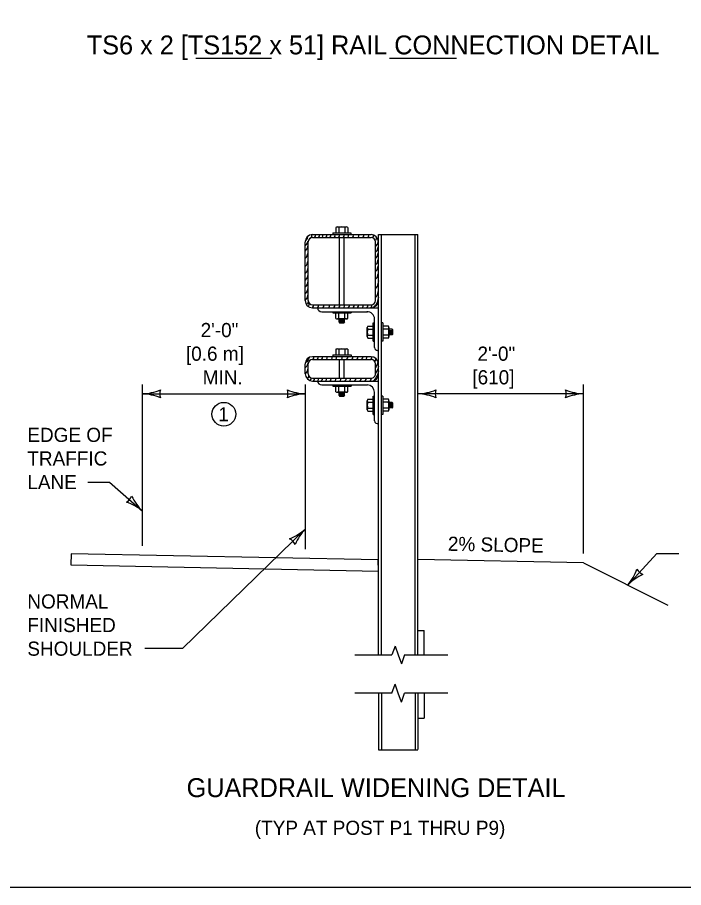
# Model space of a CAD drawing. Extents: x 49991.4 to 50021, y 49987.6 to 50011.4.
# Drawn here: x 50011.156 to 50013.977, y 49987.799 to 49991.484 of the extents above; entities that cross this region are included whole.
import ezdxf

# ---------------------------------------------------------------- set-up
doc = ezdxf.new("R2010")
doc.units = 0
for name, color, linetype in [('Level 1', 7, 'Continuous'), ('Level 2', 7, 'Continuous'), ('Level 3', 7, 'Continuous'), ('Level 6', 7, 'Continuous')]:
    doc.layers.add(name, color=color, linetype=linetype)

msp = doc.modelspace()

# ---------------------------------------------------------------- linework, layer by layer
at = {"layer": 'Level 1'}
for p, q in [((50012.4056, 49990.5649), (50012.6532, 49990.5649)), ((50012.4907, 49990.5713), (50012.5683, 49990.5713)), ((50012.4907, 49990.5713), (50012.4907, 49990.5649)), ((50012.5038, 49990.595), (50012.5038, 49990.5713)), ((50012.5038, 49990.5713), (50012.555, 49990.5713)), ((50012.5102, 49990.5966), (50012.5485, 49990.5966)), ((50012.5165, 49990.595), (50012.5165, 49990.5714)), ((50012.5423, 49990.595), (50012.5423, 49990.5714)), ((50012.555, 49990.595), (50012.555, 49990.5713)), ((50012.5683, 49990.5713), (50012.5683, 49990.5649)), ((50012.6848, 49990.5649), (50012.852, 49990.5649)), ((50012.6848, 49988.7839), (50012.6848, 49990.5649)), ((50012.6971, 49988.7839), (50012.6971, 49990.5649)), ((50012.8399, 49988.7839), (50012.8399, 49990.5649)), ((50012.852, 49988.7839), (50012.852, 49990.5649)), ((50012.3744, 49990.285), (50012.3744, 49990.5333)), ((50012.3865, 49990.285), (50012.3865, 49990.5333)), ((50012.4056, 49990.5523), (50012.6532, 49990.5523)), ((50012.5197, 49990.2665), (50012.5197, 49990.5523)), ((50012.5233, 49990.5523), (50012.5356, 49990.5523)), ((50012.5391, 49990.2665), (50012.5391, 49990.5523)), ((50012.6723, 49990.285), (50012.6723, 49990.5333)), ((50012.6848, 49990.285), (50012.6848, 49990.5333)), ((50012.4056, 49990.2665), (50012.6532, 49990.2665)), ((50012.4056, 49990.2543), (50012.6848, 49990.2543)), ((50012.4448, 49990.2379), (50012.6375, 49990.2379)), ((50012.491, 49990.2379), (50012.491, 49990.2323)), ((50012.491, 49990.2323), (50012.5686, 49990.2323)), ((50012.5553, 49990.2323), (50012.5041, 49990.2323)), ((50012.5041, 49990.2086), (50012.5041, 49990.2323)), ((50012.5168, 49990.2086), (50012.5168, 49990.2322)), ((50012.5426, 49990.2086), (50012.5426, 49990.2322)), ((50012.5553, 49990.2086), (50012.5553, 49990.2323)), ((50012.5686, 49990.2379), (50012.5686, 49990.2323)), ((50012.5489, 49990.207), (50012.5106, 49990.207)), ((50012.518, 49990.1931), (50012.518, 49990.207)), ((50012.5414, 49990.1931), (50012.518, 49990.1931)), ((50012.518, 49990.1931), (50012.5203, 49990.1908)), ((50012.5214, 49990.2037), (50012.5379, 49990.2037)), ((50012.5214, 49990.2014), (50012.5379, 49990.2014)), ((50012.5214, 49990.199), (50012.5379, 49990.199)), ((50012.5214, 49990.1967), (50012.5379, 49990.1967)), ((50012.5414, 49990.1931), (50012.5391, 49990.1908)), ((50012.5414, 49990.1931), (50012.5414, 49990.207)), ((50012.6685, 49990.0859), (50012.6685, 49990.2072)), ((50012.5203, 49990.1908), (50012.5391, 49990.1908)), ((50012.6373, 49990.1324), (50012.6373, 49990.1707)), ((50012.6388, 49990.1645), (50012.6625, 49990.1645)), ((50012.6389, 49990.1772), (50012.6626, 49990.1772)), ((50012.6626, 49990.1128), (50012.6626, 49990.1904)), ((50012.6626, 49990.1904), (50012.6685, 49990.1904)), ((50012.6626, 49990.1259), (50012.6626, 49990.1772)), ((50012.7037, 49990.1904), (50012.6971, 49990.1904)), ((50012.7037, 49990.1904), (50012.7037, 49990.1128)), ((50012.7037, 49990.1772), (50012.7037, 49990.126)), ((50012.7274, 49990.1772), (50012.7037, 49990.1772)), ((50012.7275, 49990.1645), (50012.7038, 49990.1645)), ((50012.729, 49990.1708), (50012.729, 49990.1325)), ((50012.7429, 49990.1633), (50012.729, 49990.1633)), ((50012.7322, 49990.1433), (50012.7322, 49990.1598)), ((50012.7346, 49990.1433), (50012.7346, 49990.1598)), ((50012.737, 49990.1433), (50012.737, 49990.1598)), ((50012.7393, 49990.1433), (50012.7393, 49990.1598)), ((50012.7429, 49990.1633), (50012.7429, 49990.1399)), ((50012.7429, 49990.1633), (50012.7452, 49990.161)), ((50012.7452, 49990.1422), (50012.7452, 49990.161)), ((50012.6388, 49990.1386), (50012.6625, 49990.1386)), ((50012.6389, 49990.1259), (50012.6626, 49990.1259)), ((50012.7274, 49990.126), (50012.7037, 49990.126)), ((50012.7275, 49990.1387), (50012.7038, 49990.1387)), ((50012.7429, 49990.1399), (50012.729, 49990.1399)), ((50012.7429, 49990.1399), (50012.7452, 49990.1422)), ((50012.6626, 49990.1128), (50012.6685, 49990.1128)), ((50012.7037, 49990.1128), (50012.6971, 49990.1128)), ((50012.4056, 49990.0479), (50012.6532, 49990.0479)), ((50012.491, 49990.0548), (50012.5686, 49990.0548)), ((50012.491, 49990.0548), (50012.491, 49990.0485)), ((50012.5041, 49990.0785), (50012.5041, 49990.0548)), ((50012.5041, 49990.0548), (50012.5553, 49990.0548)), ((50012.5105, 49990.0801), (50012.5488, 49990.0801)), ((50012.5168, 49990.0785), (50012.5168, 49990.0549)), ((50012.5426, 49990.0785), (50012.5426, 49990.0549)), ((50012.5553, 49990.0785), (50012.5553, 49990.0548)), ((50012.5686, 49990.0548), (50012.5686, 49990.0485)), ((50012.6848, 49990.0733), (50012.6807, 49990.0733)), ((50012.3744, 49989.975), (50012.3744, 49990.0167)), ((50012.3865, 49989.975), (50012.3865, 49990.0167)), ((50012.4056, 49990.0352), (50012.6532, 49990.0352)), ((50012.5197, 49989.9565), (50012.5197, 49990.0352)), ((50012.5233, 49990.0352), (50012.5356, 49990.0352)), ((50012.5391, 49989.9565), (50012.5391, 49990.0352)), ((50012.6723, 49989.975), (50012.6723, 49990.0167)), ((50012.4056, 49989.9565), (50012.6532, 49989.9565)), ((50012.4056, 49989.9442), (50012.6848, 49989.9442)), ((50012.4448, 49989.9279), (50012.6375, 49989.9279)), ((50012.491, 49989.9281), (50012.491, 49989.9222)), ((50012.491, 49989.9222), (50012.5686, 49989.9222)), ((50012.5553, 49989.9222), (50012.5041, 49989.9222)), ((50012.5041, 49989.8985), (50012.5041, 49989.9222)), ((50012.5168, 49989.8985), (50012.5168, 49989.9221)), ((50012.5426, 49989.8985), (50012.5426, 49989.9221)), ((50012.5553, 49989.8985), (50012.5553, 49989.9222)), ((50012.5686, 49989.9281), (50012.5686, 49989.9222)), ((50012.5489, 49989.8969), (50012.5106, 49989.8969)), ((50012.5179, 49989.883), (50012.5202, 49989.8807)), ((50012.518, 49989.883), (50012.518, 49989.8969)), ((50012.5414, 49989.883), (50012.518, 49989.883)), ((50012.5202, 49989.8807), (50012.539, 49989.8807)), ((50012.5213, 49989.8936), (50012.5378, 49989.8936)), ((50012.5213, 49989.8913), (50012.5378, 49989.8913)), ((50012.5213, 49989.8889), (50012.5378, 49989.8889)), ((50012.5213, 49989.8865), (50012.5378, 49989.8865)), ((50012.5414, 49989.883), (50012.539, 49989.8807)), ((50012.5414, 49989.883), (50012.5414, 49989.8969)), ((50012.6389, 49989.8673), (50012.6626, 49989.8673)), ((50012.6626, 49989.8029), (50012.6626, 49989.8805)), ((50012.6626, 49989.8805), (50012.6689, 49989.8805)), ((50012.6626, 49989.816), (50012.6626, 49989.8673)), ((50012.6685, 49989.7759), (50012.6685, 49989.8973)), ((50012.7037, 49989.8805), (50012.6974, 49989.8805)), ((50012.7037, 49989.8805), (50012.7037, 49989.8029)), ((50012.7037, 49989.8673), (50012.7037, 49989.8161)), ((50012.7274, 49989.8673), (50012.7037, 49989.8673)), ((50012.729, 49989.8609), (50012.729, 49989.8226)), ((50012.6373, 49989.8225), (50012.6373, 49989.8608)), ((50012.6388, 49989.8546), (50012.6625, 49989.8546)), ((50012.6388, 49989.8287), (50012.6625, 49989.8287)), ((50012.7275, 49989.8546), (50012.7038, 49989.8546)), ((50012.7275, 49989.8288), (50012.7038, 49989.8288)), ((50012.7429, 49989.8534), (50012.729, 49989.8534)), ((50012.7429, 49989.83), (50012.729, 49989.83)), ((50012.7322, 49989.8334), (50012.7322, 49989.8499)), ((50012.7346, 49989.8334), (50012.7346, 49989.8499)), ((50012.737, 49989.8334), (50012.737, 49989.8499)), ((50012.7393, 49989.8334), (50012.7393, 49989.8499)), ((50012.7429, 49989.8534), (50012.7429, 49989.83)), ((50012.7429, 49989.8534), (50012.7452, 49989.8511)), ((50012.7429, 49989.83), (50012.7452, 49989.8323)), ((50012.7452, 49989.8323), (50012.7452, 49989.8511)), ((50012.6389, 49989.816), (50012.6626, 49989.816)), ((50012.6626, 49989.8029), (50012.6689, 49989.8029)), ((50012.7037, 49989.8029), (50012.6974, 49989.8029)), ((50012.7274, 49989.8161), (50012.7037, 49989.8161)), ((50011.3834, 49989.2125), (50011.3824, 49989.1656)), ((50012.6833, 49989.1865), (50011.3834, 49989.2125)), ((50011.3824, 49989.1656), (50012.6841, 49989.1396)), ((50012.6841, 49989.1396), (50012.6833, 49989.1865)), ((50013.5529, 49989.1738), (50012.852, 49989.1878)), ((50013.5529, 49989.1738), (50013.9106, 49988.9949)), ((50012.852, 49988.8875), (50012.8788, 49988.8875)), ((50012.8788, 49988.7839), (50012.8788, 49988.8875)), ((50012.6848, 49988.6223), (50012.6848, 49988.382)), ((50012.6971, 49988.6223), (50012.6971, 49988.382)), ((50012.8399, 49988.6223), (50012.8399, 49988.3834)), ((50012.852, 49988.6223), (50012.852, 49988.3834)), ((50012.8784, 49988.6223), (50012.8784, 49988.5167)), ((50012.852, 49988.5167), (50012.8784, 49988.5167)), ((50012.6848, 49988.382), (50012.852, 49988.382))]:
    msp.add_line(p, q, dxfattribs=at)
msp.add_lwpolyline([(49999.3835, 49998.9992), (50016.7501, 49998.9992), (50016.7501, 49987.7988), (49999.3835, 49987.7988)], close=True, dxfattribs=at)
for points in [[(50012.396, 49990.5496), (50012.4008, 49990.5536), (50012.4028, 49990.5574), (50012.4028, 49990.5639)], [(50012.414, 49990.5523), (50012.4177, 49990.5579), (50012.4177, 49990.5649)], [(50012.43, 49990.5523), (50012.4342, 49990.5579), (50012.433, 49990.5649)], [(50012.4457, 49990.5523), (50012.4494, 49990.5574), (50012.4488, 49990.5639)], [(50012.4621, 49990.5523), (50012.4657, 49990.5579), (50012.4657, 49990.5639)], [(50012.4788, 49990.5523), (50012.4825, 49990.5579), (50012.4825, 49990.5639)], [(50012.4964, 49990.5523), (50012.5006, 49990.5579), (50012.5001, 49990.5639)], [(50012.516, 49990.5523), (50012.519, 49990.5574), (50012.519, 49990.5639)], [(50012.535, 49990.5523), (50012.5387, 49990.5579), (50012.5387, 49990.5639)], [(50012.5544, 49990.5523), (50012.5582, 49990.5579), (50012.5582, 49990.5639)], [(50012.5746, 49990.5523), (50012.5783, 49990.5579), (50012.5776, 49990.5639)], [(50012.5984, 49990.5523), (50012.6015, 49990.5579), (50012.6015, 49990.5649)], [(50012.6184, 49990.5523), (50012.6225, 49990.5579), (50012.622, 49990.5639)], [(50012.6388, 49990.5523), (50012.6432, 49990.5579), (50012.6422, 49990.5639)], [(50012.659, 49990.5512), (50012.6634, 49990.5568), (50012.6634, 49990.5632)], [(50012.3739, 49990.5171), (50012.3803, 49990.5227), (50012.3838, 49990.5299), (50012.3865, 49990.5373)], [(50012.3748, 49990.5359), (50012.3803, 49990.5421), (50012.3834, 49990.5479), (50012.386, 49990.5568)], [(50012.6729, 49990.5401), (50012.676, 49990.5459), (50012.676, 49990.5523)], [(50012.6733, 49990.5159), (50012.6791, 49990.5221), (50012.6817, 49990.5279), (50012.6844, 49990.5373)], [(50012.3748, 49990.4941), (50012.3803, 49990.5008), (50012.3834, 49990.5067), (50012.386, 49990.5159)], [(50012.6733, 49990.491), (50012.6787, 49990.4968), (50012.6812, 49990.503), (50012.684, 49990.5114)], [(50012.3744, 49990.4628), (50012.3803, 49990.4693), (50012.383, 49990.4751), (50012.3854, 49990.4842)], [(50012.6733, 49990.4645), (50012.6787, 49990.4709), (50012.6812, 49990.4777), (50012.684, 49990.4862)], [(50012.6733, 49990.4371), (50012.6787, 49990.4434), (50012.6812, 49990.4491), (50012.684, 49990.4583)], [(50012.3744, 49990.4287), (50012.3803, 49990.4348), (50012.383, 49990.4407), (50012.3854, 49990.4498)], [(50012.3748, 49990.399), (50012.3803, 49990.4052), (50012.3834, 49990.4112), (50012.3854, 49990.4202)], [(50012.6733, 49990.4095), (50012.6787, 49990.4153), (50012.6812, 49990.4219), (50012.684, 49990.4301)], [(50012.3748, 49990.3705), (50012.3803, 49990.3763), (50012.3834, 49990.3826), (50012.3854, 49990.3915)], [(50012.6733, 49990.3773), (50012.6787, 49990.3831), (50012.6812, 49990.3889), (50012.684, 49990.3983)], [(50012.3748, 49990.3415), (50012.3803, 49990.3479), (50012.3834, 49990.3537), (50012.3854, 49990.3626)], [(50012.6844, 49990.3683), (50012.6817, 49990.3571), (50012.6787, 49990.3466), (50012.6729, 49990.3361)], [(50012.3748, 49990.3135), (50012.3803, 49990.3197), (50012.3834, 49990.3255), (50012.3854, 49990.3346)], [(50012.3748, 49990.2866), (50012.3803, 49990.2927), (50012.3834, 49990.2986), (50012.3854, 49990.3071)], [(50012.684, 49990.3308), (50012.6817, 49990.3197), (50012.6787, 49990.3091), (50012.6729, 49990.2986)], [(50012.3875, 49990.2839), (50012.3854, 49990.276), (50012.3834, 49990.2712), (50012.3787, 49990.2696)], [(50012.3886, 49990.2607), (50012.3918, 49990.2665), (50012.3918, 49990.2723)], [(50012.4056, 49990.2543), (50012.4092, 49990.2607), (50012.4086, 49990.2665)], [(50012.4747, 49990.2543), (50012.4779, 49990.2607), (50012.4779, 49990.2665)], [(50012.4959, 49990.2543), (50012.5001, 49990.2607), (50012.4996, 49990.2665)], [(50012.5169, 49990.2543), (50012.5213, 49990.2607), (50012.5203, 49990.2665)], [(50012.5376, 49990.2549), (50012.5412, 49990.2607), (50012.5412, 49990.2665)], [(50012.5576, 49990.2549), (50012.5619, 49990.2607), (50012.5609, 49990.2669)], [(50012.5772, 49990.2543), (50012.5814, 49990.2607), (50012.5809, 49990.2665)], [(50012.5956, 49990.2543), (50012.5994, 49990.2607), (50012.5994, 49990.2665)], [(50012.6164, 49990.2543), (50012.62, 49990.2607), (50012.62, 49990.2665)], [(50012.6358, 49990.2543), (50012.64, 49990.2601), (50012.64, 49990.2665)], [(50012.6522, 49990.2543), (50012.656, 49990.2601), (50012.656, 49990.2665)], [(50012.6844, 49990.2996), (50012.6817, 49990.289), (50012.6787, 49990.278), (50012.6729, 49990.2675), (50012.6638, 49990.2569)], [(50012.4267, 49990.2543), (50012.4304, 49990.2601), (50012.4304, 49990.2659)], [(50012.4494, 49990.2543), (50012.4536, 49990.2601), (50012.4536, 49990.2659)], [(50012.4072, 49990.0352), (50012.4107, 49990.041), (50012.4107, 49990.0462)], [(50012.4256, 49990.0352), (50012.4294, 49990.041), (50012.4294, 49990.0462)], [(50012.4436, 49990.0345), (50012.4472, 49990.041), (50012.4472, 49990.0462)], [(50012.4641, 49990.0352), (50012.4673, 49990.041), (50012.4673, 49990.0462)], [(50012.4852, 49990.0352), (50012.489, 49990.041), (50012.489, 49990.0462)], [(50012.5043, 49990.0352), (50012.5074, 49990.041), (50012.5074, 49990.0462)], [(50012.5275, 49990.0352), (50012.5307, 49990.041), (50012.5307, 49990.0462)], [(50012.5513, 49990.0361), (50012.5544, 49990.0419), (50012.5544, 49990.0467)], [(50012.5724, 49990.0352), (50012.5765, 49990.041), (50012.5763, 49990.0462)], [(50012.5928, 49990.0352), (50012.5967, 49990.041), (50012.5967, 49990.0462)], [(50012.6148, 49990.0361), (50012.6184, 49990.0419), (50012.6184, 49990.0467)], [(50012.6325, 49990.0361), (50012.6358, 49990.0419), (50012.6358, 49990.0467)], [(50012.6528, 49990.0345), (50012.6563, 49990.041), (50012.6563, 49990.0467)], [(50012.3875, 49990.0219), (50012.3844, 49990.0151), (50012.3807, 49990.0076), (50012.3744, 49990.0001)], [(50012.3918, 49990.0436), (50012.3886, 49990.0361), (50012.3844, 49990.0294), (50012.3807, 49990.0256), (50012.3748, 49990.0208)], [(50012.6696, 49990.0266), (50012.674, 49990.0325), (50012.674, 49990.0389)], [(50012.6822, 49990.0263), (50012.6791, 49990.0157), (50012.6749, 49990.0059), (50012.6723, 49990.0019)], [(50012.3748, 49989.9735), (50012.3803, 49989.9797), (50012.3834, 49989.9855), (50012.3854, 49989.9939)], [(50012.6844, 49990.0072), (50012.6817, 49989.9956), (50012.6781, 49989.9855), (50012.6723, 49989.977)], [(50012.6848, 49989.9871), (50012.6817, 49989.975), (50012.6781, 49989.9655), (50012.6729, 49989.9575)], [(50012.3892, 49989.9655), (50012.3886, 49989.9616), (50012.386, 49989.9571), (50012.3824, 49989.9555)], [(50012.396, 49989.9463), (50012.3997, 49989.9521), (50012.3997, 49989.9575)], [(50012.4097, 49989.9442), (50012.414, 49989.95), (50012.4134, 49989.9559)], [(50012.4272, 49989.9449), (50012.4308, 49989.9507), (50012.4308, 49989.9559)], [(50012.443, 49989.9449), (50012.4472, 49989.9507), (50012.4472, 49989.9559)], [(50012.4616, 49989.9449), (50012.4652, 49989.9507), (50012.4652, 49989.9559)], [(50012.4804, 49989.9442), (50012.4843, 49989.95), (50012.4836, 49989.9555)], [(50012.5006, 49989.9449), (50012.5043, 49989.9507), (50012.5043, 49989.9559)], [(50012.5223, 49989.9449), (50012.5259, 49989.9507), (50012.5255, 49989.9559)], [(50012.5428, 49989.9449), (50012.5472, 49989.9507), (50012.5466, 49989.9559)], [(50012.5634, 49989.9449), (50012.5667, 49989.9507), (50012.5667, 49989.9559)], [(50012.584, 49989.9449), (50012.5881, 49989.9507), (50012.5878, 49989.9559)], [(50012.6072, 49989.9449), (50012.611, 49989.9507), (50012.611, 49989.9559)], [(50012.6279, 49989.9449), (50012.6321, 49989.9507), (50012.6316, 49989.9559)], [(50012.65, 49989.9442), (50012.6532, 49989.95), (50012.6532, 49989.9555)], [(50012.6729, 49989.9575), (50012.6644, 49989.9463)]]:
    msp.add_lwpolyline(points, dxfattribs=at)
for centre, radius, start, end in [((50012.4051, 49990.5333), 0.031, 90, 180), ((50012.6533, 49990.5333), 0.031, 0, 90), ((50012.4051, 49990.5333), 0.0186, 90, 180), ((50012.6533, 49990.5333), 0.0186, 0, 90), ((50012.4051, 49990.2851), 0.031, 180, 270), ((50012.4051, 49990.2851), 0.0186, 180, 270), ((50012.6533, 49990.2851), 0.031, 270, 0), ((50012.6533, 49990.2851), 0.0186, 270, 0), ((50012.4446, 49990.2568), 0.0189, 187.6039, 270.4744), ((50012.6361, 49990.2055), 0.0324, 2.3617, 92.3617), ((50012.6809, 49990.0857), 0.0124, 179.0939, 269.0939), ((50012.4051, 49990.0163), 0.031, 90, 180), ((50012.6533, 49990.0163), 0.031, 0, 90), ((50012.4051, 49990.0163), 0.0186, 90, 180), ((50012.6533, 49990.0163), 0.0186, 0, 90), ((50012.4054, 49989.975), 0.031, 180, 270), ((50012.4054, 49989.975), 0.0186, 180, 270), ((50012.6537, 49989.9749), 0.0186, 268.473, 0.4357), ((50012.6538, 49989.9752), 0.031, 270, 0), ((50012.4444, 49989.9463), 0.0186, 187.6623, 270), ((50012.6371, 49989.8967), 0.031, 0, 90), ((50012.6809, 49989.7759), 0.0124, 180, 287.0542)]:
    msp.add_arc(centre, radius, start, end, dxfattribs=at)
for centre, major_axis, start_param, end_param in [((50012.5102, 49990.5846), (0.0128, 0), 1.056847, 2.094396), ((50012.5294, 49990.5486), (0.0512, 0), 1.315951, 1.825641), ((50012.5486, 49990.5846), (0.0128, 0), 1.047198, 2.084746), ((50012.5105, 49990.219), (-0.0128, 0), 1.047198, 2.084746), ((50012.5297, 49990.255), (-0.0512, 0), 1.315951, 1.825641), ((50012.5489, 49990.219), (-0.0128, 0), 1.056847, 2.094396), ((50012.6493, 49990.1708), (0, 0.0128), 1.047198, 2.084746), ((50012.6852, 49990.1516), (0, 0.0512), 1.315951, 1.825641), ((50012.717, 49990.1708), (0, -0.0128), 1.056847, 2.094396), ((50012.6811, 49990.1516), (0, -0.0512), 1.315951, 1.825641), ((50012.6493, 49990.1323), (0, 0.0128), 1.056847, 2.094396), ((50012.717, 49990.1324), (0, -0.0128), 1.047198, 2.084746), ((50012.5105, 49990.0681), (0.0128, 0), 1.056847, 2.094396), ((50012.5297, 49990.0321), (0.0512, 0), 1.315951, 1.825641), ((50012.5489, 49990.0681), (0.0128, 0), 1.047198, 2.084746), ((50012.5105, 49989.9089), (-0.0128, 0), 1.047198, 2.084746), ((50012.5297, 49989.9449), (-0.0512, 0), 1.315951, 1.825641), ((50012.5489, 49989.9089), (-0.0128, 0), 1.056847, 2.094396), ((50012.6493, 49989.8609), (0, 0.0128), 1.047198, 2.084746), ((50012.717, 49989.8609), (0, -0.0128), 1.056847, 2.094396), ((50012.6493, 49989.8224), (0, 0.0128), 1.056847, 2.094396), ((50012.6852, 49989.8417), (0, 0.0512), 1.315951, 1.825641), ((50012.717, 49989.8225), (0, -0.0128), 1.047198, 2.084746), ((50012.6811, 49989.8417), (0, -0.0512), 1.315951, 1.825641)]:
    msp.add_ellipse(centre, major_axis=major_axis, ratio=0.93686, start_param=start_param, end_param=end_param, dxfattribs=at)
at = {"layer": 'Level 2'}
for p, q in [((50011.9106, 49991.3114), (50012.2312, 49991.3114)), ((50012.7311, 49991.3115), (50013.0147, 49991.3115))]:
    msp.add_line(p, q, dxfattribs=at)
msp.add_circle((50012.0299, 49989.8034), 0.0503, dxfattribs=at)
at = {"layer": 'Level 3'}
for p, q in [((50011.6852, 49989.2465), (50011.6852, 49989.93)), ((50012.3748, 49989.93), (50012.3748, 49989.2326)), ((50013.5529, 49989.2138), (50013.5529, 49989.93)), ((50011.6852, 49989.89), (50012.3748, 49989.89)), ((50013.5529, 49989.89), (50012.852, 49989.89)), ((50011.4545, 49989.5162), (50011.5459, 49989.5162)), ((50011.5459, 49989.5162), (50011.6852, 49989.3935)), ((50012.3748, 49989.3173), (50011.8544, 49988.8107)), ((50013.74, 49989.0802), (50013.8634, 49989.2141)), ((50011.8544, 49988.8107), (50011.695, 49988.8107))]:
    msp.add_line(p, q, dxfattribs=at)
msp.add_lwpolyline([(50013.8634, 49989.2141), (50013.9566, 49989.2141)], dxfattribs=at)
for centre, radius, start, end in [((50011.6737, 49990.1227), 0.233, 272.8273, 292.0772), ((50011.8134, 49989.89), 0.0548, 162.1388, 197.8612), ((50012.384, 49990.1122), 0.2223, 247.456, 267.6395), ((50012.2466, 49989.89), 0.0548, 342.1388, 17.8612), ((50012.8405, 49990.1227), 0.233, 272.8273, 292.0772), ((50012.9802, 49989.89), 0.0548, 162.1388, 197.8612), ((50013.5621, 49990.1122), 0.2223, 247.456, 267.6395), ((50013.4247, 49989.89), 0.0548, 342.1388, 17.8612), ((50011.676, 49989.6679), 0.2223, 67.456, 87.6395), ((50012.3863, 49989.6573), 0.233, 92.8273, 112.0772), ((50012.8428, 49989.6679), 0.2223, 67.456, 87.6395), ((50013.5644, 49989.6573), 0.233, 92.8273, 112.0772), ((50011.589, 49989.4782), 0.0548, 300.7491, 336.4715), ((50011.8389, 49989.5541), 0.2223, 206.0663, 226.2498), ((50011.54, 49989.2113), 0.233, 51.4376, 70.6875), ((50012.2264, 49989.4829), 0.2223, 291.6895, 311.873), ((50012.5454, 49989.1586), 0.233, 137.0608, 156.3106), ((50012.2829, 49989.2279), 0.0548, 26.3723, 62.0947), ((50013.5612, 49989.2295), 0.233, 320.157, 339.4069), ((50013.5612, 49989.2295), 0.233, 320.157, 339.4069), ((50013.8972, 49988.9229), 0.2223, 114.7857, 134.9692), ((50013.8972, 49988.9229), 0.2223, 114.7857, 134.9692), ((50013.8269, 49989.1745), 0.0548, 209.4685, 245.1909), ((50013.8269, 49989.1745), 0.0548, 209.4685, 245.1909)]:
    msp.add_arc(centre, radius, start, end, dxfattribs=at)
at = {"layer": 'Level 6'}
for p, q in [((50012.755, 49988.8218), (50012.7416, 49988.7839)), ((50012.755, 49988.8218), (50012.7684, 49988.7839)), ((50012.5848, 49988.7839), (50012.7416, 49988.7839)), ((50012.7684, 49988.7839), (50012.7819, 49988.746)), ((50012.7953, 49988.7839), (50012.7819, 49988.746)), ((50012.7953, 49988.7839), (50012.9788, 49988.7839)), ((50012.7415, 49988.6223), (50012.7549, 49988.6602)), ((50012.7684, 49988.6223), (50012.7549, 49988.6602)), ((50012.7415, 49988.6223), (50012.5848, 49988.6223)), ((50012.7818, 49988.5844), (50012.7684, 49988.6223)), ((50012.7818, 49988.5844), (50012.7952, 49988.6223)), ((50012.9784, 49988.6223), (50012.7952, 49988.6223))]:
    msp.add_line(p, q, dxfattribs=at)

# ---------------------------------------------------------------- texts
at = {"layer": 'Level 2'}
for s, height, p in [('TS6 x 2 [TS152 x 51] RAIL CONNECTION DETAIL', 0.08, (50011.4493, 49991.3275)), ('2\'-0"', 0.06, (50011.9315, 49990.13)), ('[0.6 m]', 0.06, (50011.8693, 49990.03)), ('2\'-0"', 0.06, (50013.104, 49990.03)), ('MIN.', 0.06, (50011.9402, 49989.93)), ('[610]', 0.06, (50013.0822, 49989.93)), ('1', 0.06, (50012.0067, 49989.7734)), ('EDGE OF', 0.06, (50011.1977, 49989.6862)), ('TRAFFIC', 0.06, (50011.1977, 49989.5862)), ('LANE', 0.06, (50011.1977, 49989.4862)), ('NORMAL', 0.06, (50011.1977, 49988.9807)), ('FINISHED', 0.06, (50011.1977, 49988.8807)), ('SHOULDER', 0.06, (50011.1977, 49988.7807)), ('GUARDRAIL WIDENING DETAIL', 0.08, (50011.872, 49988.182)), ('(TYP AT POST P1 THRU P9)', 0.06, (50012.161, 49988.022))]:
    msp.add_text(s, height=height, dxfattribs=at).set_placement(p)
msp.add_text('2% SLOPE', height=0.06, rotation=358.8516, dxfattribs=at).set_placement((50012.9781, 49989.2253))

doc.saveas('drawing.dxf')
